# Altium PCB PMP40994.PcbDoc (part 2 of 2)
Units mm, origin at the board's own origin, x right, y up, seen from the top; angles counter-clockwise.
Board outline 46.72 x 34.79 mm, 2 copper layers (Top Layer, Bottom Layer), stack 1.575 mm thick; 64 components, 36 nets, 150 pads, 471 vias.
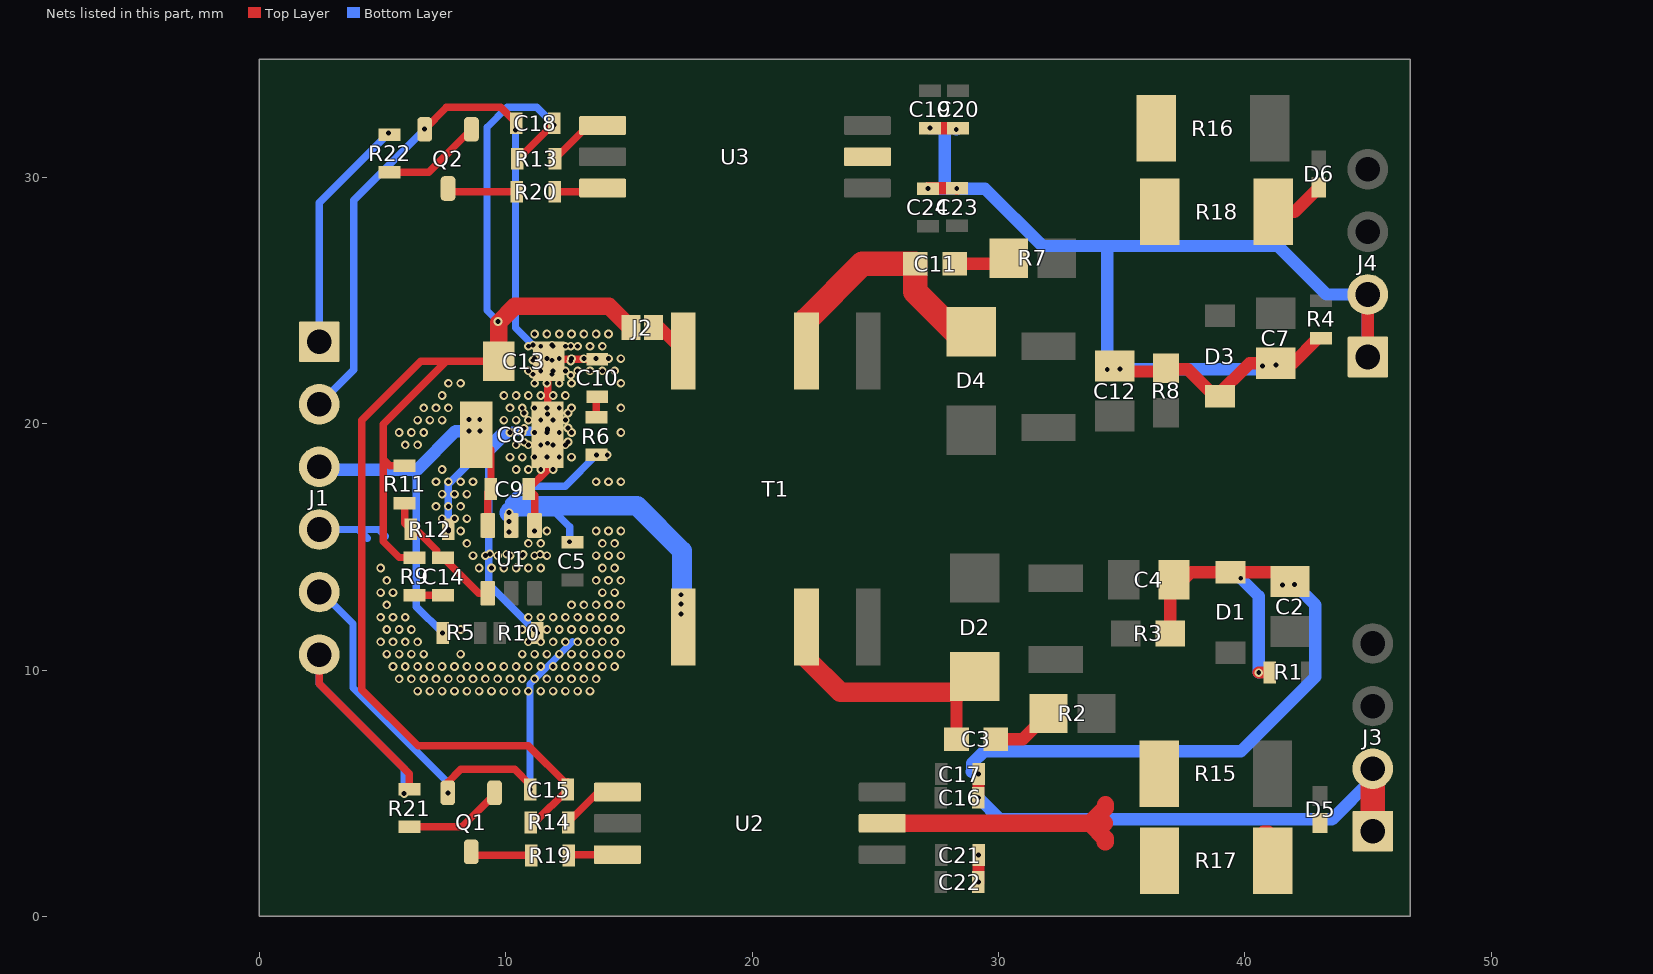
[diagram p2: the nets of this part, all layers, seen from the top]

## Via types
v1: diameter 0.35, hole 0.2, Top Layer to Bottom Layer, 471 vias

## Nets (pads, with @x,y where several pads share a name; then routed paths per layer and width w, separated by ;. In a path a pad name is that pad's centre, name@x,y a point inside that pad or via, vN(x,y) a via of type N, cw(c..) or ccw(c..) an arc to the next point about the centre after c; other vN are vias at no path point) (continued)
GND1: C8.1 C9.2 C10.2 C13.1 C15.2 C18.2 J1.2 J1.4 J1.5 Q1.2 Q2.2 R10.1 R12.1 U1.1 | length 77.9
  Top Layer w0.3: Q2.2@6.71,31.95 v1(6.71,31.96) 7.595,32.845 9.793,32.845 C18.2@10.438,32.2 ; v1(7.65,5.02) 7.65,5.44 8.18,5.97 10.37,5.97 10.988,5.352 v1(10.988,5.15) ; U1.1@11.175,15.87 11.175,17.102 C9.2@10.927,17.35 11.705,18.128 11.705,18.646 C8.1@11.705,19.55 11.705,20.146 11.705,20.646 11.705,22.146 11.705,22.499 C13.1@11.746,22.54 11.828,22.622 12.173,22.622 C10.2@13.718,22.622
  Bottom Layer w0.3: J1.5@2.43,13.17 2.51,13.17 3.8,11.88 3.8,9.29 7.65,5.44 v1(7.65,5.02) ; J1.4@2.43,15.71 4.02,15.71 ; J1.2@2.43,20.79 3.83,22.19 3.83,29.08 v1(6.71,31.96) ; 4.38,15.35 4.02,15.71 ; 5.12,15.44 4.85,15.71 4.02,15.71 ; v1(7.674,15.718) v1(7.673,16.646) 7.674,17.544 9.785,19.655 v1@10.187,19.655 ; v1(10.4,31.93) 10.4,23.9 v1(11.11,23.19) ; v1(10.988,5.15) 10.988,9.438 12.71,11.16 ; v1(11.287,11.51) 9.315,13.482 9.315,18.783 v1@10.187,19.655 ; v1@10.187,19.655 11.605,19.655 v1(11.69,19.74) 10.272,19.74 v1@10.187,19.655
  other v1: 6.423,9.146 6.923,9.146 7.423,9.146 7.923,9.146 8.423,9.146 8.923,9.146 9.423,9.146 9.923,9.146 10.423,9.146 10.923,9.146 11.423,9.146 11.923,9.146 12.423,9.146 12.923,9.146 13.423,9.146 5.673,9.646 6.173,9.646 6.673,9.646 7.173,9.646 7.673,9.646 8.173,9.646 8.673,9.646 9.173,9.646 9.673,9.646 10.173,9.646 10.673,9.646 11.173,9.646 11.673,9.646 12.173,9.646 12.673,9.646 13.173,9.646 13.673,9.646 5.423,10.146 5.923,10.146 6.423,10.146 6.923,10.146 7.423,10.146 7.923,10.146 8.423,10.146 8.923,10.146 9.423,10.146 9.923,10.146 10.423,10.146 10.923,10.146 11.423,10.146 11.923,10.146 12.423,10.146 12.923,10.146 13.423,10.146 13.923,10.146 14.423,10.146 5.173,10.646 5.673,10.646 6.173,10.646 6.673,10.646 8.173,10.646 10.673,10.646 11.173,10.646 11.673,10.646 12.173,10.646 12.673,10.646 13.173,10.646 13.673,10.646 14.173,10.646 14.673,10.646 4.923,11.146 5.423,11.146 5.923,11.146 6.423,11.146 10.923,11.146 11.423,11.146 11.923,11.146 12.423,11.146 12.923,11.146 13.423,11.146 13.923,11.146 14.423,11.146 5.173,11.646 5.673,11.646 6.173,11.646 8.173,11.646 10.673,11.646 11.173,11.646 11.673,11.646 12.173,11.646 12.673,11.646 13.173,11.646 13.673,11.646 14.173,11.646 14.673,11.646 4.923,12.146 5.423,12.146 5.923,12.146 10.923,12.146 11.423,12.146 11.923,12.146 12.423,12.146 12.923,12.146 13.423,12.146 13.923,12.146 14.423,12.146 5.173,12.646 12.673,12.646 13.173,12.646 13.673,12.646 14.173,12.646 14.673,12.646 4.923,13.146 5.423,13.146 13.923,13.146 14.423,13.146 5.173,13.646 13.673,13.646 14.173,13.646 14.673,13.646 4.923,14.146 8.923,14.146 9.423,14.146 9.923,14.146 10.423,14.146 10.923,14.146 11.423,14.146 13.923,14.146 14.423,14.146 8.673,14.646 9.173,14.646 9.673,14.646 10.173,14.646 10.673,14.646 11.173,14.646 11.673,14.646 13.673,14.646 14.173,14.646 14.673,14.646 9.36,14.72 10.04,14.71 10.706,14.7 11.4,14.7 8.423,15.146 10.923,15.146 11.423,15.146 13.923,15.146 14.423,15.146 7.673,15.646 8.173,15.646 11.173,15.646 11.673,15.646 13.673,15.646 14.173,15.646 14.673,15.646 7.423,16.146 7.923,16.146 8.423,16.146 7.173,16.646 8.173,16.646 7.423,17.146 7.923,17.146 8.423,17.146 7.173,17.646 7.673,17.646 8.173,17.646 8.673,17.646 13.673,17.646 14.173,17.646 14.673,17.646 7.423,18.146 10.423,18.146 10.923,18.146 11.423,18.146 11.923,18.146 10.173,18.646 10.673,18.646 11.173,18.646 11.673,18.646 12.173,18.646 12.673,18.646 5.923,19.146 6.423,19.146 10.423,19.146 10.923,19.146 11.423,19.146 11.923,19.146 12.423,19.146 11.7,19.21 10.75,19.25 12.53,19.26 5.673,19.646 6.173,19.646 6.673,19.646 10.173,19.646 10.673,19.646 11.173,19.646 11.673,19.646 12.173,19.646 12.673,19.646 14.673,19.646 11.7,19.78 10.75,19.82 12.53,19.83 6.423,20.146 6.923,20.146 7.423,20.146 9.923,20.146 10.423,20.146 10.923,20.146 11.423,20.146 11.923,20.146 12.423,20.146 11.7,20.39 10.75,20.43 12.53,20.44 6.673,20.646 7.173,20.646 7.673,20.646 10.173,20.646 10.673,20.646 11.173,20.646 11.673,20.646 12.173,20.646 12.673,20.646 14.673,20.646 7.423,21.146 9.923,21.146 10.423,21.146 10.923,21.146 11.423,21.146 11.923,21.146 12.423,21.146 7.673,21.646 8.173,21.646 11.173,21.646 11.673,21.646 12.173,21.646 12.673,21.646 14.673,21.646 12.64,21.97 11.11,22.01 11.88,22.01 10.923,22.146 11.423,22.146 11.923,22.146 12.423,22.146 12.923,22.146 13.423,22.146 13.923,22.146 14.423,22.146 12.64,22.54 11.11,22.58 11.88,22.58 11.173,22.646 11.673,22.646 12.173,22.646 12.673,22.646 13.173,22.646 13.673,22.646 14.173,22.646 14.673,22.646 10.923,23.146 11.423,23.146 11.923,23.146 12.423,23.146 12.64,23.15 12.923,23.146 13.423,23.146 13.923,23.146 11.88,23.19 11.173,23.646 11.673,23.646 12.173,23.646 12.673,23.646 13.173,23.646 13.673,23.646 14.173,23.646
NetC3_1: C3.1 R2.1 | length 2.6
  Top Layer w0.508: C3.1@29.9,7.2 31,7.2 R2.1@32.04,8.24
NetC3_2: C3.2 D2.1 T1.6 | length 12.2
  Top Layer w0.5: T1.6@22.213,10.267 22.213,10.477 T1.6@22.213,11.75 ; C3.2@28.3,7.2 D2.1@28.3,8.93 ; D2.1@29.04,9.74 28.4,9.1 28.3,9 D2.1@28.3,8.93 ; D2.1@29.08,9.71 D2.1@28.3,8.93
  Top Layer w0.8: T1.6@22.213,10.477 23.59,9.1 D2.1@28.4,9.1
NetC10_1: C10.1 R6.1 | length 0.9
  Top Layer w0.3: R6.1@13.684,20.262 13.684,21.064 C10.1@13.718,21.098
NetC11_1: C11.1 R7.1 | length 2.3
  Top Layer w0.5: C11.1@28.23,26.49 30.19,26.49 R7.1@30.42,26.72
NetC11_2: C11.2 D4.1 T1.3 | length 10.7
  Top Layer w1: T1.3@22.213,22.95 22.213,24.223 24.48,26.49 C11.2@26.63,26.49 26.63,25.36 28.25,23.74 D4.1@28.9,23.74
NetC14_1: C14.1 R9.1 | length 1.2
  Top Layer w0.3: R9.1@6.302,13.046 6.31,13.038 C14.1@7.46,13.038
NetD5_1: D5.1 R17.2 | length 0.2
  Top Layer w0.5: R17.2@40.76,3.44 R17.2@40.95,3.44
NetD6_1: D6.1 R18.2 | length 2.3
  Top Layer w0.5: R18.2@41.16,28.6 42.02,28.6 D6.1@43.01,29.59
NetJ2_1: J2.1 T1.1 | length 1.9
  Top Layer w0.3: T1.1@16.947,22.95 T1.1@17.213,22.95
  Top Layer w0.5: J2.1@15.997,23.9 16.263,23.9 T1.1@17.213,22.95
NetQ1_1: Q1.1 R21.1 | length 4.1
  Top Layer w0.3: R21.1@6.09,3.638 8.226,3.638 9.55,4.962 Q1.1@9.55,5.02
NetQ1_3: Q1.3 R19.1 | length 2.5
  Top Layer w0.3: Q1.3@8.6,2.62 8.74,2.48 R19.1@11.038,2.48
NetQ2_1: Q2.1 R22.1 | length 4
  Top Layer w0.3: R22.1@5.29,30.218 6.878,30.218 Q2.1@8.61,31.95
NetQ2_3: Q2.3 R20.1 | length 2.9
  Top Layer w0.3: Q2.3@7.66,29.55 7.79,29.42 R20.1@10.458,29.42
NetR13_1: R13.1 U3.1 | length 2.5
  Top Layer w0.3: R13.1@12.002,30.816 R13.1@12.002,30.76 13.352,32.11 U3.1@13.935,32.11
NetR14_1: R14.1 U2.1 | length 2.5
  Top Layer w0.3: R14.1@12.532,3.82 13.762,5.05 U2.1@14.535,5.05
NetR15_1: R15.1 R17.1 U2.5 | length 11.1
  Top Layer w0.7: U2.5@25.285,3.78 33.72,3.78 ; 34.31,3.78 33.72,3.78 ; 34.34,3.02 34.34,3.16 33.72,3.78 ; 34.35,4.53 34.35,4.41 33.72,3.78 ; R15.1@36.11,6.72 R15.1@36.16,6.67
NetR16_1: R16.1 R18.1 U3.5
NetR19_2: R19.2 U2.3 | length 2
  Top Layer w0.3: R19.2@12.562,2.48 12.592,2.51 U2.3@14.535,2.51
NetR20_2: R20.2 U3.3 | length 2
  Top Layer w0.3: R20.2@11.982,29.42 13.785,29.42 U3.3@13.935,29.57
PWMA: J1.6 R21.2 | length 14.1
  Top Layer w0.3: J1.6@2.43,10.63 2.43,9.452 6.09,5.792 R21.2@6.09,5.162
  Bottom Layer w0.3: J1.6@2.43,10.63 2.43,9.452 5.88,6.002 v1(5.88,4.99)
PWMB: J1.1 R22.2 | length 9.6
  Bottom Layer w0.3: J1.1@2.43,23.33 2.43,28.98 v1(5.25,31.8)
SGNDA: C2.1 C4.2 C16.2 C17.2 C21.2 C22.2 D1.2 J3.1 J3.2 R1.1 R3.2 | length 54.9
  Top Layer w0.5: v1(29.192,1.392) 29.192,2.482 v1(29.2,2.49) ; v1(29.192,4.82) 29.192,5.837 29.202,5.847 v1(29.202,5.78) ; R3.2@36.98,11.38 36.98,13.14 37.818,13.978 D1.2@39.43,13.978 41.458,13.978 C2.1@41.84,13.596 ; v1(40.57,9.9) 41.01,9.9 R1.1@41.02,9.91
  Top Layer w1: J3.1@45.2,3.46 J3.2@45.2,6
  Bottom Layer w0.5: 28.92,5.88 28.93,5.89 28.93,6.22 29.41,6.7 39.84,6.7 42.87,9.73 42.87,12.64 42.05,13.46 v1@42.01,13.46 ; v1(29.192,4.82) 30.072,3.94 43.4,3.94 43.54,3.94 45.2,5.6 J3.2@45.2,6 ; v1(39.84,13.73) 40.57,13 v1(40.57,9.9) ; 41.36,13.48 v1(42.03,13.48) v1@42.01,13.46 ; v1(41.54,13.46) v1@42.01,13.46
SGNDB: C7.1 C12.2 C19.2 C20.2 C23.2 C24.2 D3.2 J4.1 J4.2 R4.1 R8.2 | length 53.2
  Top Layer w0.5: v1(27.139,29.543) 27.158,29.562 C23.2@28.329,29.562 v1(28.31,29.543) ; v1(27.23,32.001) C20.2@28.364,32.001 ; C12.2@34.51,22.3 34.69,22.12 34.94,22.12 36.817,22.12 36.907,22.21 37.693,22.21 38.82,21.083 40.192,22.454 C7.1@41.26,22.454 41.953,22.454 R4.1@42.96,23.461 ; J4.1@45,22.71 J4.2@45,25.25
  Bottom Layer w0.5: v1(27.139,29.543) v1@27.146,29.543 ; v1@27.142,29.54 v1@27.146,29.543 ; v1(27.23,32.001) 27.82,32.001 ; v1(28.291,31.953) 28.243,32.001 27.82,32.001 ; v1(34.94,22.23) v1@34.92,22.21 ; v1(40.73,22.345) 40.775,22.39 v1(41.27,22.39) 41.09,22.21 v1@34.92,22.21 ; J4.1@45,22.71 J4.2@45,25.25 43.32,25.25 41.355,27.215 34.335,27.215 ; v1@27.146,29.543 27.829,29.543 ; 27.82,32.001 27.82,29.552 27.829,29.543 ; 27.829,29.543 v1(28.31,29.543) 29.457,29.543 31.785,27.215 34.335,27.215 ; 34.335,27.215 34.42,27.13 v1(34.42,22.21) v1@34.92,22.21
SW: C5.1 R6.2 T1.8 U1.2 | length 20.4
  Bottom Layer w0.3: v1(10.13,16.04) 10.13,16.816 10.784,17.47 12.416,17.47 v1(13.684,18.738) v1(14.121,18.738) ; v1(10.14,15.6) v1(10.14,16.39) 12.02,16.39 12.598,15.812 v1(12.598,15.21) ; 10.33,16.58 10.33,16.68
  Bottom Layer w0.8: v1(10.14,16.39) 10.33,16.58 10.421,16.671 15.33,16.671 17.16,14.841 17.16,12.1
  other v1: 17.12,12.28 17.12,12.68 17.12,13.06
VCC1: C13.2 C15.1 C18.1 J2.2 R9.2 R11.2 R13.2 R14.2 | length 61.8
  Top Layer w0.3: R11.2@5.9,18.302 5.298,18.302 5.03,18.57 ; R9.2@6.302,14.57 5.68,14.57 5.03,15.22 5.03,18.57 ; C13.2@9.69,23.324 9.714,23.3 C13.2@9.714,22.54 7.59,22.54 ; R13.2@10.478,30.76 10.522,30.76 C18.1@11.962,32.2 ; R14.2@11.008,3.82 11.182,3.82 C15.1@12.512,5.15 C15.1@12.512,5.338 ; C15.1@12.512,5.478 C15.1@12.512,5.338 ; 5.03,18.57 5.03,19.98 7.59,22.54 ; 7.59,22.54 6.55,22.54 4.16,20.15 4.16,9.21 6.44,6.93 10.92,6.93 C15.1@12.512,5.338
  Top Layer w0.7: C13.2@9.714,23.3 9.714,24.114 10.37,24.77 14.196,24.77 J2.2@15.066,23.9
  Bottom Layer w0.3: v1(9.69,24.15) 9.24,24.6 9.24,32.03 10.055,32.845 11.255,32.845 v1(11.97,32.13)
VIN: C8.2 C9.1 J1.3 R5.2 U1.3 | length 19.6
  Top Layer w0.3: C8.2@8.805,19.55 9.403,18.952 C9.1@9.403,17.35 9.275,17.222 U1.3@9.275,15.87
  Bottom Layer w0.3: 6.37,18.04 6.37,12.58 v1(7.44,11.51) ; v1(8.51,19.7) v1(8.51,20.18) v1(8.947,20.18) 8.96,20.167 v1(8.96,19.7) v1(8.51,19.7)
  Bottom Layer w0.5: J1.3@2.43,18.25 2.55,18.13 6.397,18.13 7.967,19.7 v1(8.51,19.7)
VSENSE: C14.2 R11.1 R12.2 U1.4 | length 5.6
  Top Layer w0.3: R11.1@5.9,16.778 5.9,15.968 R12.2@6.15,15.718 6.15,15.62 6.446,15.62 7.208,14.858 7.208,14.562 C14.2@7.46,14.562 8.902,13.12 U1.4@9.275,13.12
pads on no net: U2.2 U3.2

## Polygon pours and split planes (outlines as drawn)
GateA on Bottom Layer "BOTTOM_LAYER_GATEA_P044" (solid, remove dead copper, pour order 44): 43.645,11.945 43.645,7.9 44.215,7.33 45.995,7.33 46.445,7.78 46.445,11.96 45.725,12.68 44.38,12.68
GateB on Bottom Layer "BOTTOM_LAYER_GATEB_P042" (solid, remove dead copper, pour order 42): 43.76,27.89 44.76,26.89 45.56,26.89 46.1,27.43 46.1,30.99 45.41,31.68 44.12,31.68 43.76,30.99
VIN on Bottom Layer "BOTTOM_LAYER_VIN_P038" (solid, remove dead copper, pour order 38): 1.47,18.99 1.47,17.65 1.89,17.23 3.69,17.23 4.13,17.67 6.58,17.67 8.08,19.17 9.001,19.17 9.372,19.54 9.372,20.518 9.306,20.584 8.343,20.584 6.399,18.64 4.24,18.64 3.6,19.28 1.76,19.28
GND1 on Bottom Layer "BOTTOM_LAYER_GND1_P036" (solid, remove dead copper, pour order 36): 3.45,16.54 4.39,17.48 5.27,17.48 5.56,17.19 5.56,13.84 5.22,13.5 4.32,13.5 3.14,14.68 1.53,14.68 1.53,16.51 1.56,16.54
SGNDB on Bottom Layer "BOTTOM_LAYER_SGNDB_P026" (solid, remove dead copper, pour order 26): 29.09,29.79 29.09,26.73 29.577,26.243 34.067,21.753 46.023,21.753 46.343,22.073 46.29,25.1 41.28,29.79
-8V_B on Bottom Layer "BOTTOM_LAYER_-8V_B_P022" (solid, remove dead copper, pour order 22): 24.98,24.43 24.98,20.169 26.479,18.67 35.15,18.67 35.792,19.312 35.792,20.678 35,21.47 34.05,21.47 33.62,21.9 33.62,24.51 32.19,25.94 26.49,25.94
-8V_A on Bottom Layer "BOTTOM_LAYER_-8V_A_P018" (solid, remove dead copper, pour order 18): 24.9,12.95 24.9,9.89 26.66,8.13 34.91,8.13 36.39,9.61 36.39,13.31 34.67,15.03 26.98,15.03
SGNDA on Bottom Layer "BOTTOM_LAYER_SGNDA_P012" (solid, remove dead copper, pour order 12): 28.645,6.16 28.645,1.1 45.52,1.1 46.415,1.995 46.415,6.45 45.925,6.94 41.935,6.94 41.155,6.16
GND1 on Bottom Layer "BOTTOM_LAYER_GND1_P010" (solid, remove dead copper, pour order 10): 4.25,25.22 4.25,9.73 6.04,7.94 13.91,7.94 15.61,9.64 15.61,25 13.87,26.74 5.77,26.74
NetR15_1 on Top Layer "TOP_LAYER_NETR15_1_P040" (solid, remove dead copper, pour order 40): 34.03,6.021 35.245,7.23 37.175,7.23 37.745,6.66 37.745,0.97 37.445,0.67 36.46,0.67 35.306,0.67 34.03,1.827
GateA on Top Layer "TOP_LAYER_GATEA_P032" (solid, remove dead copper, pour order 32): 39.794,4.606 40.14,4.26 43.1,4.26 46.41,7.57 46.41,11.81 45.83,12.39 44.2,12.39 43.59,11.78 43.59,8.91 42.15,7.47 40.46,7.47 39.794,6.934
NetD5_1 on Top Layer "TOP_LAYER_NETD5_1_P030" (solid, remove dead copper, pour order 30): 40.142,3.892 42.122,3.892 42.527,4.297 43.347,4.297 43.917,3.727 43.917,1.307 43.367,0.757 40.072,0.757 39.787,1.042 39.787,3.537
GateB on Top Layer "TOP_LAYER_GATEB_P028" (solid, remove dead copper, pour order 28): 39.33,33.442 39.33,30.82 39.82,30.33 43.172,30.33 44.08,29.421 44.08,27.07 44.42,26.73 45.66,26.73 45.66,26.829 46.27,27.439 46.27,32.62 44.79,34.1 39.864,34.1
NetR16_1 on Top Layer "TOP_LAYER_NETR16_1_P024" (solid, remove dead copper, pour order 24): 23.754,31.36 32.627,31.36 35.538,34.12 37.38,34.12 37.84,33.66 37.84,27.61 37.39,27.16 35.72,27.16 32.6,30.28 23.889,30.28 23.609,30.56 23.609,31.186
-8V_B on Top Layer "TOP_LAYER_-8V_B_P020" (solid, remove dead copper, pour order 20): 26,20.928 26,19.28 26.53,18.75 37.5,18.75 37.842,19.092 37.842,20.818 37.47,21.19 26.22,21.19
-8V_A on Top Layer "TOP_LAYER_-8V_A_P016" (solid, remove dead copper, pour order 16): 25.43,13.08 26.2,12.31 29.83,12.31 31.39,10.75 36.04,10.75 36.04,14.82 25.43,14.82
GND1 on Top Layer "TOP_LAYER_GND1_P008" (solid, remove dead copper, pour order 8): 4.5,24.3 4.5,10.39 5.97,8.92 13.66,8.92 15.07,10.33 15.07,24.15 13.67,25.55 5.75,25.55

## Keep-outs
Keep-Out Layer:
  text ".Layer_Name" at 14.656,-19.696 h1.52

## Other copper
Top Layer:
  text ".Layer_Name" at 14.656,-19.696 h1.52
Bottom Layer:
  pour cut-out: 39.9,3.38 39.9,1.07 39.94,1.11 42.51,1.11 42.51,3.441 42.489,3.42 39.98,3.42
  pour cut-out: 39.9,4.33 42.651,4.33 43.05,4.729 43.05,6.96 40.76,6.96 39.9,6.1
  pour cut-out: 34.33,3.51 34.33,1.31 34.58,1.06 37.64,1.06 37.64,3.496 34.41,3.496
  pour cut-out: 34.35,6.123 34.35,4.59 37.66,4.59 37.66,6.159 34.442,6.159 34.423,6.14
  pour cut-out: 40.36,29.8 40.36,27.33 40.57,27.12 41.91,27.12 41.95,27.16 41.95,29.9 41.94,29.89 40.34,29.89
  pour cut-out: 33.254,29.709 35.7,27.263 35.7,27.215 37.645,27.215 37.67,27.19 38.1,27.62 38.1,29.69 37.95,29.84 33.23,29.84 33.23,29.682 33.282,29.63
  text ".Layer_Name" at 14.656,-19.696 h1.52

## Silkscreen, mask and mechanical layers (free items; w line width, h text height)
Top Overlay:
  text ".Layer_Name" at 14.656,-19.696 h0.4
Bottom Overlay:
  text ".Layer_Name" at 14.656,-19.696 h1.52
Top Paste:
  text ".Layer_Name" at 14.656,-19.696 h1.52
Bottom Paste:
  text ".Layer_Name" at 14.656,-19.696 h1.52
Top Solder:
  text ".Layer_Name" at 14.656,-19.696 h1.52
  text ".Layer_Name" at 14.656,-19.696 h1.52
Bottom Solder:
  text ".Layer_Name" at 14.656,-19.696 h1.52
Drill Guide:
  text ".Layer_Name" at 14.656,-19.696 h1.52
M1 Board Outline:
  the board outline again, w0.254
  text ".Layer_Name" at 14.656,-19.696 h1.52
M2 Board Dimensions:
  rectangle: 3.175,-8.05 12.7,-4.875
  rectangle: 0,-4.875 3.175,-1.7
  lines w0.178: 0,-4.875 25.4,-4.875 ; 3.175,-8.05 3.175,-1.7 ; 6.35,-8.05 6.35,-1.7 ; 12.7,-8.05 12.7,-1.7 ; 19.05,-8.05 19.05,-1.7 ; 0,-8.05 0,-1.7 25.4,-1.7 25.4,-8.05 0,-8.05
  text ".Layer_Name" at 14.656,-19.696 h1.52
M3 3D STEP Top:
  text ".Layer_Name" at 14.656,-19.696 h1.52
M4 3D STEP Bottom:
  text ".Layer_Name" at 14.656,-19.696 h1.52
M5 Assembly Top:
  lines w0.254: -7.417,-21.516 160.223,-21.516 ; -7.417,-16.352 160.274,-16.352 ; -7.417,-11.187 -7.417,-26.681 94.31,-26.681 160.274,-26.681 160.274,-11.187 -7.404,-11.187 -7.404,-26.681 32.614,-26.681 ; 55.194,-26.681 55.194,-11.187 ; 87.376,-16.352 87.376,-11.187 ; 108.712,-16.352 108.712,-11.187 ; 124.511,-26.846 124.511,-21.694
  text "PCB VIEWED FROM TOP SIDE" at -5.804,-14.544 h1.52
  text "BOARD #:" at 57.099,-14.544 h1.52
  text ".PRJ_Number" at 70.955,-14.544 h1.52
  text "REV:" at 92.405,-14.544 h1.52
  text ".PCB_Rev" at 99.809,-14.544 h1.52
  text "SVN REV:" at 113.69,-14.544 h1.52
  text ".VersionControl_RevNumber" at 126.543,-14.544 h1.52
  text "TID #:" at 57.099,-19.709 h1.52
  text ".TID" at 70.955,-19.709 h1.52
  text "PLOT NAME =" at -5.804,-24.924 h1.52
  text ".plot_File_Name" at 14.656,-24.924 h1.52
  text "GENERATED    :" at 57.15,-24.924 h1.52
  text ".Print_Date" at 79.235,-24.924 h1.52
  text ".Print_Time" at 97.752,-24.924 h1.52
  text "TEXAS INSTRUMENTS" at 129.87,-24.924 h1.52
M6 Assembly Bottom:
  lines w0.254: -7.429,-16.364 160.261,-16.364 ; -7.379,-21.529 160.261,-21.529 ; 28.334,-26.859 28.334,-21.707 ; 44.133,-16.364 44.133,-11.2 ; 65.468,-16.364 65.468,-11.2 ; 97.65,-26.694 97.65,-11.2 ; 120.231,-26.694 160.249,-26.694 160.249,-11.2 -7.429,-11.2 -7.429,-26.694 58.534,-26.694 160.261,-26.694 160.261,-11.2
  text "COMPONENTS MARKED 'DNP' SHOULD NOT BE POPULATED." at 154.991,-5.967 h1.52
  text ".VariantName" at 128.473,-8.914 h1.52
  text "ASSEMBLY VARIANT:" at 154.864,-8.914 h1.52
  text ".VersionControl_RevNumber" at 26.302,-14.557 h1.52
  text "SVN REV:" at 39.154,-14.557 h1.52
  text ".PCB_Rev" at 53.035,-14.557 h1.52
  text "REV:" at 60.439,-14.557 h1.52
  text ".PRJ_Number" at 81.89,-14.557 h1.52
  text "BOARD #:" at 95.745,-14.557 h1.52
  text "PCB VIEWED FROM BOTTOM SIDE" at 158.648,-14.557 h1.52
  text ".TID" at 81.89,-19.721 h1.52
  text "TID #:" at 95.745,-19.721 h1.52
  text "TEXAS INSTRUMENTS" at 22.974,-24.937 h1.52
  text ".Print_Time" at 55.093,-24.937 h1.52
  text ".Print_Date" at 73.609,-24.937 h1.52
  text "GENERATED    :" at 95.694,-24.937 h1.52
  text ".plot_File_Name" at 138.189,-24.937 h1.52
  text "PLOT NAME =" at 158.648,-24.937 h1.52
M9 Title Sheet:
  drawing of 57 lines, arcs and shapes, not listed
  text "1" at 18.792,206.237 h1.78
  text "2" at 82.182,206.237 h1.78
  text "3" at 145.411,206.237 h1.78
  text "4" at 209.08,206.237 h1.78
  text "5" at 272.555,206.237 h1.78
  text "6" at 336.182,206.237 h1.78
  text "A" at -10.579,177.205 h1.78
  text "A" at 365.341,177.205 h1.78
  text "B" at -10.579,116.753 h1.78
  text "B" at 365.341,116.753 h1.78
  text "C" at -10.579,56.428 h1.78
  text "C" at 365.341,56.428 h1.78
  text "PROJECT TITLE:" at 288.125,9.159 h1.14
  text ".PRJ_Title" at 289.395,5.772 h1.78
  text "DESIGNED FOR:" at 288.125,1.513 h1.14
  text ".PRJ_Customer" at 289.395,-2.043 h1.78
  text "D" at -10.579,-3.77 h1.78
  text "D" at 365.341,-3.77 h1.78
  text "FILE NAME:" at 288.125,-6.107 h1.14
  text ".PCB_File_Name_No_Path" at 289.395,-9.155 h1.78
  text "Texas Instruments (TI) and/or its licensors do not warrant the accuracy or completeness of this specification" at 161.9,-13.266 h1.14
  text "ENGINEER:" at 288.125,-13.473 h1.14
  text "LAYOUT BY:" at 326.352,-13.473 h1.14
  text "or any information contained therein. TI and/or its licensors do not warrant that this design will meet" at 160.757,-16.127 h1.14
  text ".PRJ_Engineer" at 289.395,-17.41 h1.78
  text ".PCB_Layout" at 327.635,-17.41 h1.78
  text "the specifications, will be suitable for your application or fit for any particular purpose, or will operate in" at 160.757,-18.989 h1.14
  text ".Layer_Name" at 14.656,-19.696 h1.52
  text "ALTIUM DESIGNER VERSION:" at 326.352,-21.347 h1.14
  text "an implementation. TI and/or its licensors do not warrant that the design is production worthy. You should" at 160.757,-21.851 h1.14
  text "completely validate and test your design implementation to confirm the system functionality for your application." at 161.9,-24.712 h1.14
  text ".print_Scale" at 289.395,-24.733 h1.78
  text ".Application_BuildNumber" at 327.635,-24.733 h1.78
  text "1" at 18.792,-29.983 h1.78
  text "2" at 82.182,-29.983 h1.78
  text "3" at 145.411,-29.983 h1.78
  text "4" at 209.08,-29.983 h1.78
  text "5" at 272.555,-29.983 h1.78
  text "6" at 336.182,-29.983 h1.78
M10 Fab Notes:
  drawing of 189 lines, arcs and shapes, not listed
  text "DESIGN INFORMATION" at 314.503,163.557 h1.52
  text "MIN. TRACK WIDTH:" at 298.131,160.201 h1.52
  text "8" at 325.976,160.201 h1.52
  text "MIL" at 329.907,160.201 h1.52
  text "MIN. CLEARANCE:" at 298.131,157.048 h1.52
  text "0.2" at 324.452,157.048 h1.52
  text "mm" at 329.907,157.048 h1.52
  text "MIN. VIA PAD SIZE:" at 298.131,153.895 h1.52
  text "24" at 325.214,153.895 h1.52
  text "MIL" at 329.907,153.895 h1.52
  text "0.05mm (2MIL)" at 315.784,150.596 h1.52
  text "MINIMUM ANNULAR RING" at 289.769,150.387 h1.52
  text "EXTERNAL" at 333.768,150.387 h1.52
  text "PER" at 294.849,147.59 h1.52
  text "IPC-D-275 CLASS 2 LEVEL C" at 300.437,147.59 h1.52
  text "MIL, HOLES" at 338.238,145.038 h1.52
  text "+/-" at 328.27,144.819 h1.52
  text "+/-" at 349.961,144.819 h1.52
  text "REGISTRATION TOLERANCES:" at 289.769,144.792 h1.52
  text "METAL" at 320.243,144.792 h1.52
  text "5" at 334.879,144.793 h1.52
  text "3" at 356.037,144.793 h1.52
  text "MIL" at 358.99,144.792 h1.52
  text "HOLE SIZE TOLERANCE (UNLESS OTHERWISE SPECIFIED):" at 289.769,142.295 h1.52
  text "+/-" at 349.961,142.222 h1.52
  text "3" at 356.037,142.195 h1.52
  text "MIL" at 358.99,142.195 h1.52
  text "MATERIAL:" at 287.87,138.699 h1.52
  text "FR-4 High Tg" at 312.926,135.434 h1.52
  text "X" at 309.257,135.232 h1.52
  text "FR-408" at 298.563,135.117 h1.52
  text "OTHER" at 336.358,135.117 h1.52
  text "62 MIL (1.6mm) +/-10%" at 306.694,131.484 h1.52
  text "X" at 303.643,131.422 h1.52
  text "THICKNESS:" at 289.769,131.275 h1.52
  text "OTHER" at 339.33,131.275 h1.52
  text "TOLERANCE:" at 289.769,127.762 h1.52
  text "X" at 311.314,127.762 h1.52
  text "ANSI IPC-6012 TYPE 3 CLASS 2" at 315.836,127.762 h1.52
  text "OTHER +/-" at 315.835,124.099 h1.52
  text "BOW & TWIST:" at 289.769,120.412 h1.52
  text "X" at 311.314,120.412 h1.52
  text "ANSI IPC-6012 TYPE 3 CLASS 2" at 315.836,120.412 h1.52
  text "OTHER +/-" at 315.835,116.686 h1.52
  text "DRILLING:" at 287.87,113.368 h1.52
  text "NC_DRILL FILES" at 332.599,110.696 h1.52
  text "REFERENCE:" at 289.769,110.596 h1.52
  text "X" at 306.463,110.594 h1.52
  text "AS SHOWN" at 310.984,110.596 h1.52
  text "X" at 329.348,110.596 h1.52
  text "OTHER" at 340.168,106.983 h1.52
  text "PTH COPPER THICKNESS:" at 289.761,106.893 h1.52
  text "X" at 318.697,106.893 h1.52
  text "20-30 um" at 321.948,106.893 h1.52
  text "BOARD FINISH:" at 287.87,103.144 h1.52
  text "SILKSCREEN:" at 291.812,100.347 h1.52
  text "X" at 316.14,100.347 h1.52
  text "TOP" at 319.112,100.347 h1.52
  text "X" at 329.094,100.347 h1.52
  text "BOTTOM" at 332.091,100.347 h1.52
  text "SILKSCREEN COLOR:" at 291.812,96.405 h1.52
  text "X" at 316.115,96.405 h1.52
  text "WHITE" at 319.112,96.405 h1.52
  text "OTHER" at 332.091,96.405 h1.52
  text "X" at 319.442,92.762 h1.52
  text "GREEN" at 322.439,92.762 h1.52
  text "OTHER" at 338.136,92.762 h1.52
  text "SOLDER RESIST COLOR:" at 291.812,92.587 h1.52
  text "X" at 319.442,88.844 h1.52
  text "MATTE" at 322.439,88.844 h1.52
  text "SEMI-GLOSS" at 338.125,88.827 h1.52
  text "IMMERSION GOLD (ENIG)" at 314.819,84.455 h1.52
  text "ENEPIG" at 348.793,84.272 h1.52
  text "SURFACE FINISH:" at 287.87,84.246 h1.52
  text "X" at 310.298,84.246 h1.52
  text "IMM. TIN/SILVER OR EQUIV" at 296.24,80.759 h1.52
  text "OTHER" at 332.599,80.659 h1.52
  text "ARRAY/PANEL:" at 287.87,76.712 h1.52
  text "CUT AND TRIM PER M1 BOARD OUTLINE" at 314.819,76.503 h1.52
  text "N.C. ROUTE" at 314.819,73.05 h1.52
  text "X" at 332.295,73.05 h1.52
  text "V. SCORE" at 336.816,73.05 h1.52
  text "CERTIFICATION:" at 287.87,69.77 h1.52
  text "MATERIALS AND WORKMANSHIP FOR ALL PCBS" at 306.285,69.77 h1.52
  text "TO MEET OR EXCEED THE REQUIREMENTS OF:" at 306.285,67.381 h1.52
  text "X" at 297.078,64.113 h1.52
  text "ANSI IPC-A-600F CLASS ->" at 300.329,64.113 h1.52
  text "X" at 342.188,64.113 h1.52
  text "2" at 344.982,64.113 h1.52
  text "1" at 336.981,64.075 h1.52
  text "3" at 353.973,64.075 h1.52
  text "X" at 317.702,60.362 h1.52
  text "RoHS" at 320.953,60.362 h1.52
  text "OTHER" at 337.321,60.362 h1.52
  text "PER ORDER" at 347.407,60.362 h1.52
  text "ALL BOARDS MUST MEET OR EXCEED UL94-V0 REQUIREMENTS." at 288.569,56.455 h1.52
  text "PCB MUST BEAR THE UL94V-0 UL REGISTERED MATERIAL ID NUMBER" at 288.569,53.507 h1.52
  text "ADDITIONAL REQUIREMENTS:" at 287.87,49.204 h1.52
  text "MICROSECTION:" at 289.769,46.483 h1.52
  text "YES" at 312.775,46.483 h1.52
  text "REQUIRED" at 334.657,42.817 h1.52
  text "BARE BOARD ELEC. TEST:" at 289.769,42.744 h1.52
  text "NONE" at 322.935,42.744 h1.52
  text "X" at 331.66,42.744 h1.52
  text "PER ORDER" at 349.693,42.744 h1.52
  text "XX MIL VIAS REQUIRE NON-CONDUCTIVE FILL AND PLANARIZE" at 294.04,37.538 h1.5
  text "XX MIL VIAS REQUIRE CONDUCTIVE FILL AND PLANARIZE" at 294.243,34.897 h1.52
  text "OUTER XX MIL TRACES REQUIRE 50 OHM SINGLE-ENDED IMPEDANCE" at 294.218,30.747 h1.47
  text "LAYER 2 & 3 (INNER LAYERS) XX MIL WIDE, XX MIL SPACE / TRACES REQUIRE 100 OHM DIFFERENTIAL IMPEDANCE" at 294.015,24.76 h1.52
  text ".Layer_Name" at 14.656,-19.696 h1.52
M11 Gerber Information:
  lines w0.254: -7.417,-21.516 160.223,-21.516 ; -7.417,-16.352 160.274,-16.352 ; -7.417,-11.187 -7.417,-26.681 94.31,-26.681 160.274,-26.681 160.274,-11.187 -7.404,-11.187 -7.404,-26.681 32.614,-26.681 ; 55.194,-26.681 55.194,-11.187 ; 87.376,-16.352 87.376,-11.187 ; 108.712,-16.352 108.712,-11.187 ; 124.511,-26.846 124.511,-21.694
  text "ALL ARTWORK VIEWED FROM TOP SIDE" at -5.804,-14.544 h1.52
  text "BOARD #:" at 57.099,-14.544 h1.52
  text ".PRJ_Number" at 70.955,-14.544 h1.52
  text "REV:" at 92.405,-14.544 h1.52
  text ".PCB_Rev" at 99.809,-14.544 h1.52
  text "SVN REV:" at 113.69,-14.544 h1.52
  text ".VersionControl_RevNumber" at 126.543,-14.544 h1.52
  text "LAYER NAME =" at -5.804,-19.696 h1.52
  text "TID #:" at 57.099,-19.709 h1.52
  text ".TID" at 70.955,-19.709 h1.52
  text "PLOT NAME =" at -5.804,-24.924 h1.52
  text ".plot_File_Name" at 14.656,-24.924 h1.52
  text "GENERATED    :" at 57.15,-24.924 h1.52
  text ".Print_Date" at 79.235,-24.924 h1.52
  text ".Print_Time" at 97.752,-24.924 h1.52
  text "TEXAS INSTRUMENTS" at 129.87,-24.924 h1.52
M12 Stackup:
  drawing of 191 lines, arcs and shapes, not listed
  text "Layer" at 249.215,185.56 h1.52
  text "Name" at 259.626,185.56 h1.52
  text "Material" at 283.242,185.56 h1.52
  text "Thickness" at 305.08,185.56 h1.52
  text "Constant" at 321.586,185.56 h1.52
  text "Board Layer Stack" at 336.06,185.56 h1.52
  text "1" at 249.215,182.512 h1.52
  text "Top Overlay" at 259.626,182.512 h1.52
  text "2" at 249.215,179.464 h1.52
  text "Top Solder" at 259.626,179.464 h1.52
  text "Solder Resist" at 283.242,179.464 h1.52
  text "0.40mil" at 305.08,179.464 h1.52
  text "3.5" at 321.586,179.464 h1.52
  text "3" at 249.215,176.416 h1.52
  text "Top Layer" at 259.626,176.416 h1.52
  text "Copper" at 283.242,176.416 h1.52
  text "1.40mil" at 305.08,176.416 h1.52
  text "4" at 249.215,173.368 h1.52
  text "Dielectric1" at 259.626,173.368 h1.52
  text "FR-4" at 283.242,173.368 h1.52
  text "59.20mil" at 305.08,173.368 h1.52
  text "4.8" at 321.586,173.368 h1.52
  text "5" at 249.215,170.32 h1.52
  text "Bottom Layer" at 259.626,170.32 h1.52
  text "Copper" at 283.242,170.32 h1.52
  text "1.40mil" at 305.08,170.32 h1.52
  text "6" at 249.215,167.272 h1.52
  text "Bottom Solder" at 259.626,167.272 h1.52
  text "Solder Resist" at 283.242,167.272 h1.52
  text "0.40mil" at 305.08,167.272 h1.52
  text "3.5" at 321.586,167.272 h1.52
  text "7" at 249.215,164.224 h1.52
  text "Bottom Overlay" at 259.626,164.224 h1.52
  text ".Layer_Name" at 14.656,-19.696 h1.52
M13 Component Bodies Top:
  text ".Layer_Name" at 14.656,-19.696 h1.52
M14 Component Bodies Bottom:
  text ".Layer_Name" at 14.656,-19.696 h1.52
M15 Courtyards Top:
  text ".Layer_Name" at 14.656,-19.696 h1.52
M16 Courtyards Bottom:
  text ".Layer_Name" at 14.656,-19.696 h1.52
Drill Drawing:
  lines w0.254: 135.537,86.514 136.94,86.514 136.94,87.917 135.537,87.917 135.537,86.514 ; 135.537,91.075 136.94,91.075 136.238,89.671 135.537,91.075
  lines w0.305: 134.264,85.566 216.344,85.566 ; 134.264,91.882 216.344,91.882 ; 142.846,82.409 142.846,95.04 ; 151.279,82.409 151.279,95.04 ; 167.448,82.409 167.448,95.04 ; 174.03,82.409 174.03,95.04 ; 183.559,82.409 183.559,95.04 ; 201.957,82.409 201.957,95.04 ; 134.264,82.409 216.344,82.409 216.344,95.04 134.264,95.04 134.264,82.409
  text "Symbol" at 136.159,92.829 h1.83
  text "Quantity" at 143.793,92.829 h1.83
  text "Finished Hole Size" at 152.226,92.829 h1.83
  text "Plated" at 168.395,92.829 h1.83
  text "Hole Type" at 174.977,92.829 h1.83
  text "Drill Layer Pair" at 184.506,92.829 h1.83
  text "Hole Tolerance" at 202.904,92.829 h1.83
  text "471" at 143.793,89.671 h1.52
  text "7.87mil (0.200mm)" at 152.226,89.671 h1.52
  text "PTH" at 168.395,89.671 h1.52
  text "Round" at 174.977,89.671 h1.52
  text "Top Layer - Bottom Layer" at 184.506,89.671 h1.52
  text "14" at 143.793,86.514 h1.52
  text "39.37mil (1.000mm)" at 152.226,86.514 h1.52
  text "PTH" at 168.395,86.514 h1.52
  text "Round" at 174.977,86.514 h1.52
  text "Top Layer - Bottom Layer" at 184.506,86.514 h1.52
  text "485 Total" at 143.793,83.356 h1.52
  text ".Layer_Name" at 14.656,-19.696 h1.52
M17 Embedded Cavity:
  text ".Layer_Name" at 14.656,-19.696 h1.52
M18 Embedded Assembly:
  text ".Layer_Name" at 14.656,-19.696 h1.52
M19 Embedded Keepout:
  text ".Layer_Name" at 14.656,-19.696 h1.52

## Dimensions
-0.02,-0.11 to -0.06,34.43 on M2 Board Dimensions
-0.004,-0.148 to 46.766,-0.108 on M2 Board Dimensions
0,-8.05 to 25.4,-8.05 on M2 Board Dimensions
